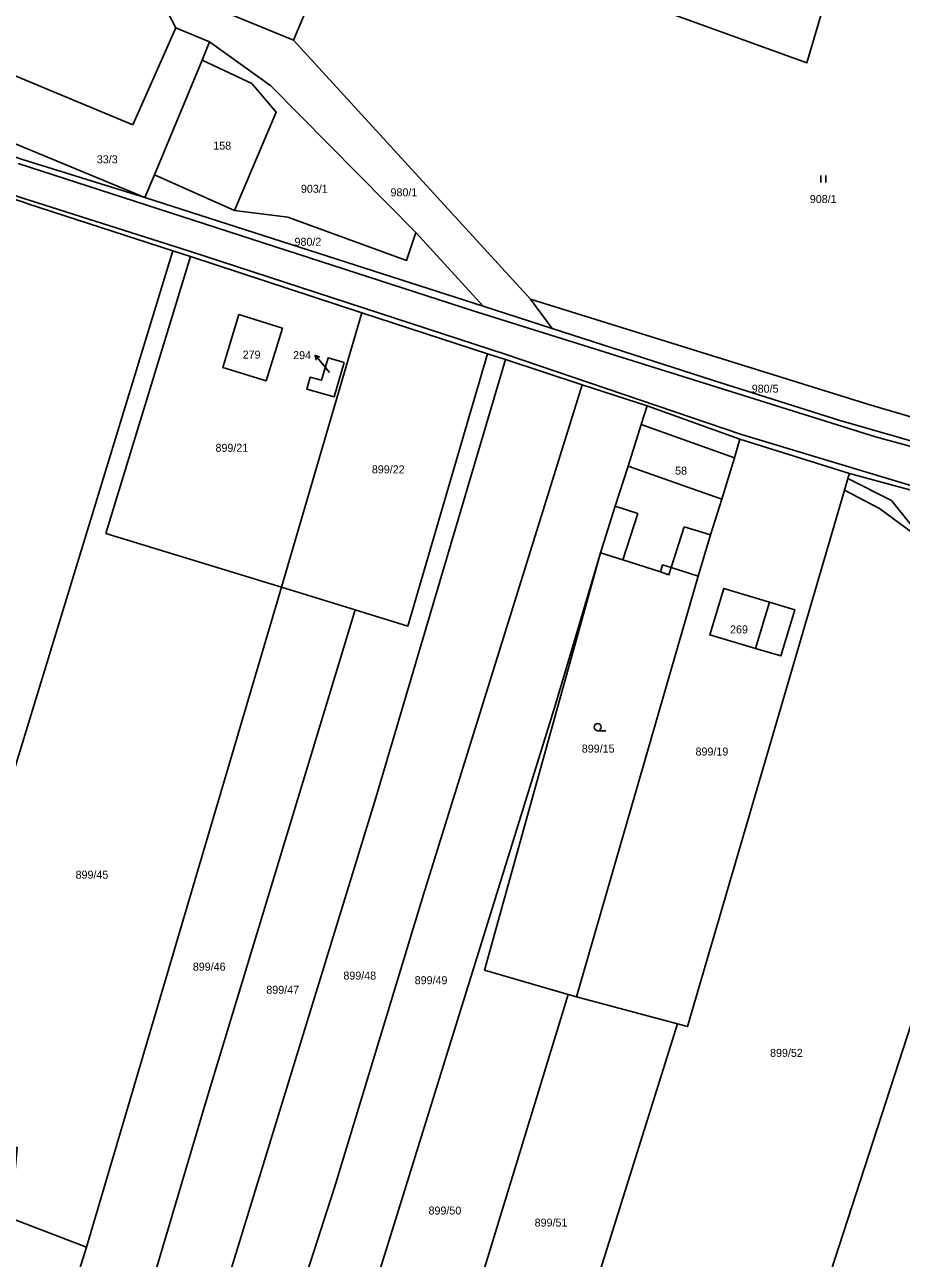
# Model space of a CAD drawing. Extents: x -7483133 to -743907, y -11317770 to -1129777.
# Drawn here: x -750919.9 to -750733.8, y -1131658.7 to -1131396.7 of the extents above; entities that cross this region are included whole.
import ezdxf

# ---------------------------------------------------------------- set-up
doc = ezdxf.new("R2010")
doc.units = 0
for name, color, linetype in [('Hranice parcel', 7, 'Continuous'), ('Parcelní čísla', 7, 'Continuous'), ('Pop  PČ popisy', 7, 'Continuous'), ('Vnitřní kresba', 7, 'Continuous'), ('Značky kultur', 7, 'Continuous')]:
    doc.layers.add(name, color=color, linetype=linetype)

msp = doc.modelspace()

# ---------------------------------------------------------------- linework, layer by layer
at = {"layer": 'Hranice parcel'}
for p, q in [((-750862.86, -1131399.97), (-750849.02, -1131366.87)), ((-750862.86, -1131399.97), (-750812.53, -1131455.02)), ((-750882.28, -1131404.22), (-750880.67, -1131400.34)), ((-750892.4, -1131428.59), (-750882.28, -1131404.22)), ((-750871.68, -1131409.18), (-750882.28, -1131404.22)), ((-750932.55, -1131417.63), (-750894.41, -1131433.45)), ((-750894.41, -1131433.45), (-750892.4, -1131428.59)), ((-750892.4, -1131428.59), (-750875.37, -1131436.2)), ((-750822.63, -1131456.51), (-750894.41, -1131433.45)), ((-750836.9, -1131440.83), (-750822.63, -1131456.51)), ((-750943.7, -1131625.46), (-750888.52, -1131444.72)), ((-750884.72, -1131445.97), (-750902.74, -1131504.79)), ((-750888.52, -1131444.72), (-750884.72, -1131445.97)), ((-750884.72, -1131445.97), (-750848.33, -1131457.88)), ((-750807.97, -1131461.22), (-750812.53, -1131455.02)), ((-750807.97, -1131461.22), (-750822.63, -1131456.51)), ((-750865.44, -1131516.21), (-750848.33, -1131457.88)), ((-750848.33, -1131457.88), (-750821.7, -1131466.6)), ((-750838.58, -1131524.43), (-750821.7, -1131466.6)), ((-750821.7, -1131466.6), (-750817.89, -1131467.84)), ((-750817.89, -1131467.84), (-750801.59, -1131473.18)), ((-750801.59, -1131473.18), (-750787.79, -1131477.7)), ((-750768.13, -1131484.76), (-750787.79, -1131477.7)), ((-750744.87, -1131492.04), (-750768.13, -1131484.76)), ((-750794.57, -1131499), (-750797.73, -1131508.87)), ((-750902.74, -1131504.79), (-750865.44, -1131516.21)), ((-750802.78, -1131603.21), (-750776.98, -1131513.82)), ((-750906.83, -1131656.39), (-750865.44, -1131516.21)), ((-750865.44, -1131516.21), (-750849.78, -1131521)), ((-750849.78, -1131521), (-750838.58, -1131524.43)), ((-750804.59, -1131602.69), (-750802.78, -1131603.21)), ((-750802.78, -1131603.21), (-750781.38, -1131608.92)), ((-750805.4, -1131685.58), (-750781.38, -1131608.92)), ((-750913.67, -1131677.99), (-750906.83, -1131656.39))]:
    msp.add_line(p, q, dxfattribs=at)
for points in [[(-750736.77, -1131350.61), (-750740.43, -1131359.24), (-750753.88, -1131404.78), (-750813.96, -1131383.01), (-750849.02, -1131366.87)], [(-750890.35, -1131392.66), (-750885.34, -1131390.64), (-750876.17, -1131394.52), (-750862.86, -1131399.97)], [(-750880.67, -1131400.34), (-750887.88, -1131397.38), (-750890.35, -1131392.66)], [(-750894.41, -1131433.45), (-750920.38, -1131425.31), (-750939.71, -1131418.8), (-750957.49, -1131412.77), (-750975.81, -1131399.68)], [(-750836.9, -1131440.83), (-750867.69, -1131409.71), (-750880.67, -1131400.34)], [(-750875.37, -1131436.2), (-750866.54, -1131415.3), (-750871.68, -1131409.18)], [(-750935.55, -1131429.45), (-750919.74, -1131434.58), (-750919.26, -1131434.74), (-750888.52, -1131444.72)], [(-750875.37, -1131436.2), (-750864.07, -1131437.61), (-750838.87, -1131446.78), (-750836.9, -1131440.83)], [(-750812.53, -1131455.02), (-750740.7, -1131477.39), (-750718.37, -1131483.96), (-750693.19, -1131490.82)], [(-750865.21, -1131461.17), (-750874.44, -1131458.29), (-750877.86, -1131469.5), (-750868.66, -1131472.33), (-750865.21, -1131461.17)], [(-750693.19, -1131490.82), (-750700.17, -1131493.87), (-750714.32, -1131490.16), (-750747.12, -1131480.73), (-750773.74, -1131472.31), (-750807.97, -1131461.22)], [(-750887.18, -1131697.19), (-750845.36, -1131560.95), (-750817.89, -1131467.84)], [(-750852.14, -1131468.44), (-750854.27, -1131475.77), (-750860.06, -1131474.15), (-750859.32, -1131471.58), (-750856.89, -1131472.24), (-750855.5, -1131467.49), (-750852.14, -1131468.44)], [(-750873.81, -1131706.37), (-750865.79, -1131679.65), (-750854.15, -1131643.66), (-750835.27, -1131581.48), (-750801.59, -1131473.18)], [(-750787.79, -1131477.7), (-750789.07, -1131481.65), (-750791.84, -1131490.48), (-750794.57, -1131499)], [(-750771.95, -1131497.49), (-750769.24, -1131488.68), (-750768.13, -1131484.76)], [(-750745.91, -1131495.61), (-750745.17, -1131493.07), (-750744.87, -1131492.04)], [(-750744.87, -1131492.04), (-750726.78, -1131496.93), (-750724.05, -1131497.67)], [(-750781.38, -1131608.92), (-750779.2, -1131609.5), (-750745.91, -1131495.61)], [(-750745.91, -1131495.61), (-750738.46, -1131499.46), (-750731.45, -1131504.65), (-750708.07, -1131534.34)], [(-750776.98, -1131513.82), (-750774.32, -1131505.07), (-750771.95, -1131497.49)], [(-750859.94, -1131710.9), (-750838.94, -1131643.24), (-750807.23, -1131541.08), (-750797.73, -1131508.87)], [(-750797.73, -1131508.87), (-750822.3, -1131597.55), (-750804.59, -1131602.69)], [(-750797.73, -1131508.87), (-750792.94, -1131510.4), (-750784.99, -1131512.95), (-750783.17, -1131513.53), (-750782.68, -1131512), (-750776.98, -1131513.82)], [(-750764.79, -1131529.23), (-750759.41, -1131530.78), (-750756.45, -1131520.98), (-750761.81, -1131519.36), (-750771.52, -1131516.43), (-750774.5, -1131526.3), (-750764.79, -1131529.23)], [(-750900, -1131688.02), (-750881.19, -1131624.56), (-750849.78, -1131521)], [(-750763.62, -1131706.58), (-750750.64, -1131667.2), (-750727.2, -1131595.02), (-750708.07, -1131534.34)], [(-750828.65, -1131680.98), (-750824.53, -1131667.99), (-750804.59, -1131602.69)], [(-750906.83, -1131656.39), (-750922.88, -1131650.23), (-750921.5, -1131635.24), (-750943.7, -1131625.46)]]:
    msp.add_lwpolyline(points, dxfattribs=at)
at = {"layer": 'Pop  PČ popisy'}
for p, q in [((-750856.36, -1131469.2), (-750858.29, -1131466.9)), ((-750858.29, -1131466.9), (-750857.26, -1131467.35)), ((-750858.29, -1131466.9), (-750858.03, -1131467.99)), ((-750855.21, -1131470.58), (-750856.36, -1131469.2))]:
    msp.add_line(p, q, dxfattribs=at)
at = {"layer": 'Vnitřní kresba'}
for p, q in [((-750896.95, -1131417.98), (-750887.88, -1131397.38)), ((-750896.95, -1131417.98), (-750927.44, -1131405.33)), ((-750963.22, -1131419.19), (-750919.46, -1131433.85)), ((-750824.74, -1131457.49), (-750921.32, -1131426.22)), ((-750919.46, -1131433.85), (-750918.99, -1131434.01)), ((-750918.99, -1131434.01), (-750884.96, -1131444.78)), ((-750817.74, -1131466.77), (-750884.96, -1131444.78)), ((-750739.31, -1131484.25), (-750824.74, -1131457.49)), ((-750767.75, -1131483.73), (-750817.74, -1131466.77)), ((-750789.07, -1131481.65), (-750769.24, -1131488.68)), ((-750730.88, -1131494.84), (-750767.75, -1131483.73)), ((-750700.09, -1131494.96), (-750739.31, -1131484.25)), ((-750791.84, -1131490.48), (-750771.95, -1131497.49)), ((-750745.17, -1131493.07), (-750735.89, -1131497.78)), ((-750789.78, -1131500.54), (-750794.57, -1131499)), ((-750735.89, -1131497.78), (-750706.11, -1131535.06)), ((-750789.78, -1131500.54), (-750792.94, -1131510.4)), ((-750779.96, -1131503.36), (-750782.68, -1131512)), ((-750774.32, -1131505.07), (-750779.96, -1131503.36)), ((-750784.99, -1131512.95), (-750784.5, -1131511.41)), ((-750784.5, -1131511.41), (-750782.68, -1131512)), ((-750761.81, -1131519.36), (-750764.79, -1131529.23))]:
    msp.add_line(p, q, dxfattribs=at)
at = {"layer": 'Značky kultur'}
for p, q in [((-750750.89, -1131430.21), (-750750.89, -1131428.71)), ((-750749.89, -1131430.21), (-750749.89, -1131428.71)), ((-750798.28, -1131546.66), (-750796.53, -1131546.66))]:
    msp.add_line(p, q, dxfattribs=at)
msp.add_circle((-750798.28, -1131545.91), 0.75, dxfattribs=at)

# ---------------------------------------------------------------- texts
at = {"layer": 'Parcelní čísla'}
for s, p in [('158', (-750879.89, -1131423.25)), ('33/3', (-750904.62, -1131426.16)), ('903/1', (-750861.29, -1131432.41)), ('980/1', (-750842.27, -1131433.17)), ('908/1', (-750753.26, -1131434.59)), ('980/2', (-750862.65, -1131443.67)), ('279', (-750873.66, -1131467.64)), ('294', (-750862.94, -1131467.75)), ('980/5', (-750765.59, -1131474.87)), ('899/21', (-750879.43, -1131487.43)), ('899/22', (-750846.23, -1131492.01)), ('58', (-750781.85, -1131492.28)), ('269', (-750770.19, -1131526.01)), ('899/15', (-750801.66, -1131551.32)), ('899/19', (-750777.52, -1131551.94)), ('899/45', (-750909.13, -1131578.1)), ('899/46', (-750884.24, -1131597.64)), ('899/48', (-750852.28, -1131599.53)), ('899/49', (-750837.14, -1131600.51)), ('899/47', (-750868.64, -1131602.54)), ('899/52', (-750761.7, -1131615.95)), ('899/50', (-750834.2, -1131649.43)), ('899/51', (-750811.67, -1131651.99))]:
    msp.add_text(s, height=1.7, dxfattribs=at).set_placement(p)

doc.saveas('drawing.dxf')
